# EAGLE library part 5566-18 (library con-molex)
Mini FIT connector 18 pol Source: http://www.molex.com
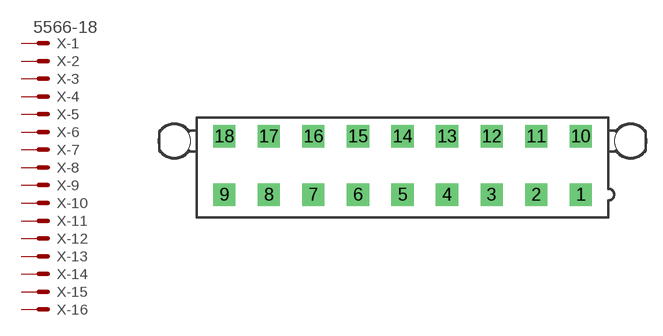
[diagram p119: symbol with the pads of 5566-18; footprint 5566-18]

Designator prefix X; gates -1=MV -2=M -3=M -4=M -5=M -6=M -7=M -8=M -9=M -10=M -11=M -12=M -13=M -14=M -15=M -16=M -17=M -18=M

## 5566-18 (OC_FARNELL: unknown; OC_NEWARK: unknown)  [5566-18]
1  -1:S  pas
2  -2:S  pas
3  -3:S  pas
4  -4:S  pas
5  -5:S  pas
6  -6:S  pas
7  -7:S  pas
8  -8:S  pas
9  -9:S  pas
10  -10:S  pas
11  -11:S  pas
12  -12:S  pas
13  -13:S  pas
14  -14:S  pas
15  -15:S  pas
16  -16:S  pas
17  -17:S  pas
18  -18:S  pas

## Footprint 5566-18 (pad centres in mm)
Mini FIT connector 18 pol Source: http://www.molex.com
drill 1.4 square: 1 16.8,-2.75; 2 12.6,-2.75; 3 8.4,-2.75; 4 4.2,-2.75; 5 0,-2.75; 6 -4.2,-2.75; 7 -8.4,-2.75; 8 -12.6,-2.75; 9 -16.8,-2.75; 10 16.8,2.75; 11 12.6,2.75; 12 8.4,2.75; 13 4.2,2.75; 14 0,2.75; 15 -4.2,2.75; 16 -8.4,2.75; 17 -12.6,2.75; 18 -16.8,2.75
hole 3 at 21.5,2.29
hole 3 at -21.5,2.29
